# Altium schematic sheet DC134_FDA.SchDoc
size 431 x 279 mm; Date: Not shown in title block; ApprovedBy: Not shown in title block; CheckedBy: Not shown in title block; Author: Not shown in title block; CompanyName: Not shown in title block; Engineer: Not shown in title block; Organization: Not shown in title block; Address1: Not shown in title block; Address2: Not shown in title block; Address3: Not shown in title block; Address4: Not shown in title block; DocumentNumber: 3; Revision: Use project parameter SCH_Rev; SheetNumber: 3; SheetTotal: 9; PageSetup: Record=PageOptions¦CenterHorizontal=True¦CenterVertical=True¦PrintScale=1.00¦XCorrection=1.00¦YCorrection=1.00¦PrintKind=0¦BorderSize=5000000¦LeftOffset=0¦BottomOffset=0¦Orientation=2¦PaperLength=1000¦PaperWidth=1000¦Scale=100¦PaperSource=15¦PrintQuality=600¦MediaType=1¦DitherType=10¦PaperKind=Letter¦PrintScaleMode=1
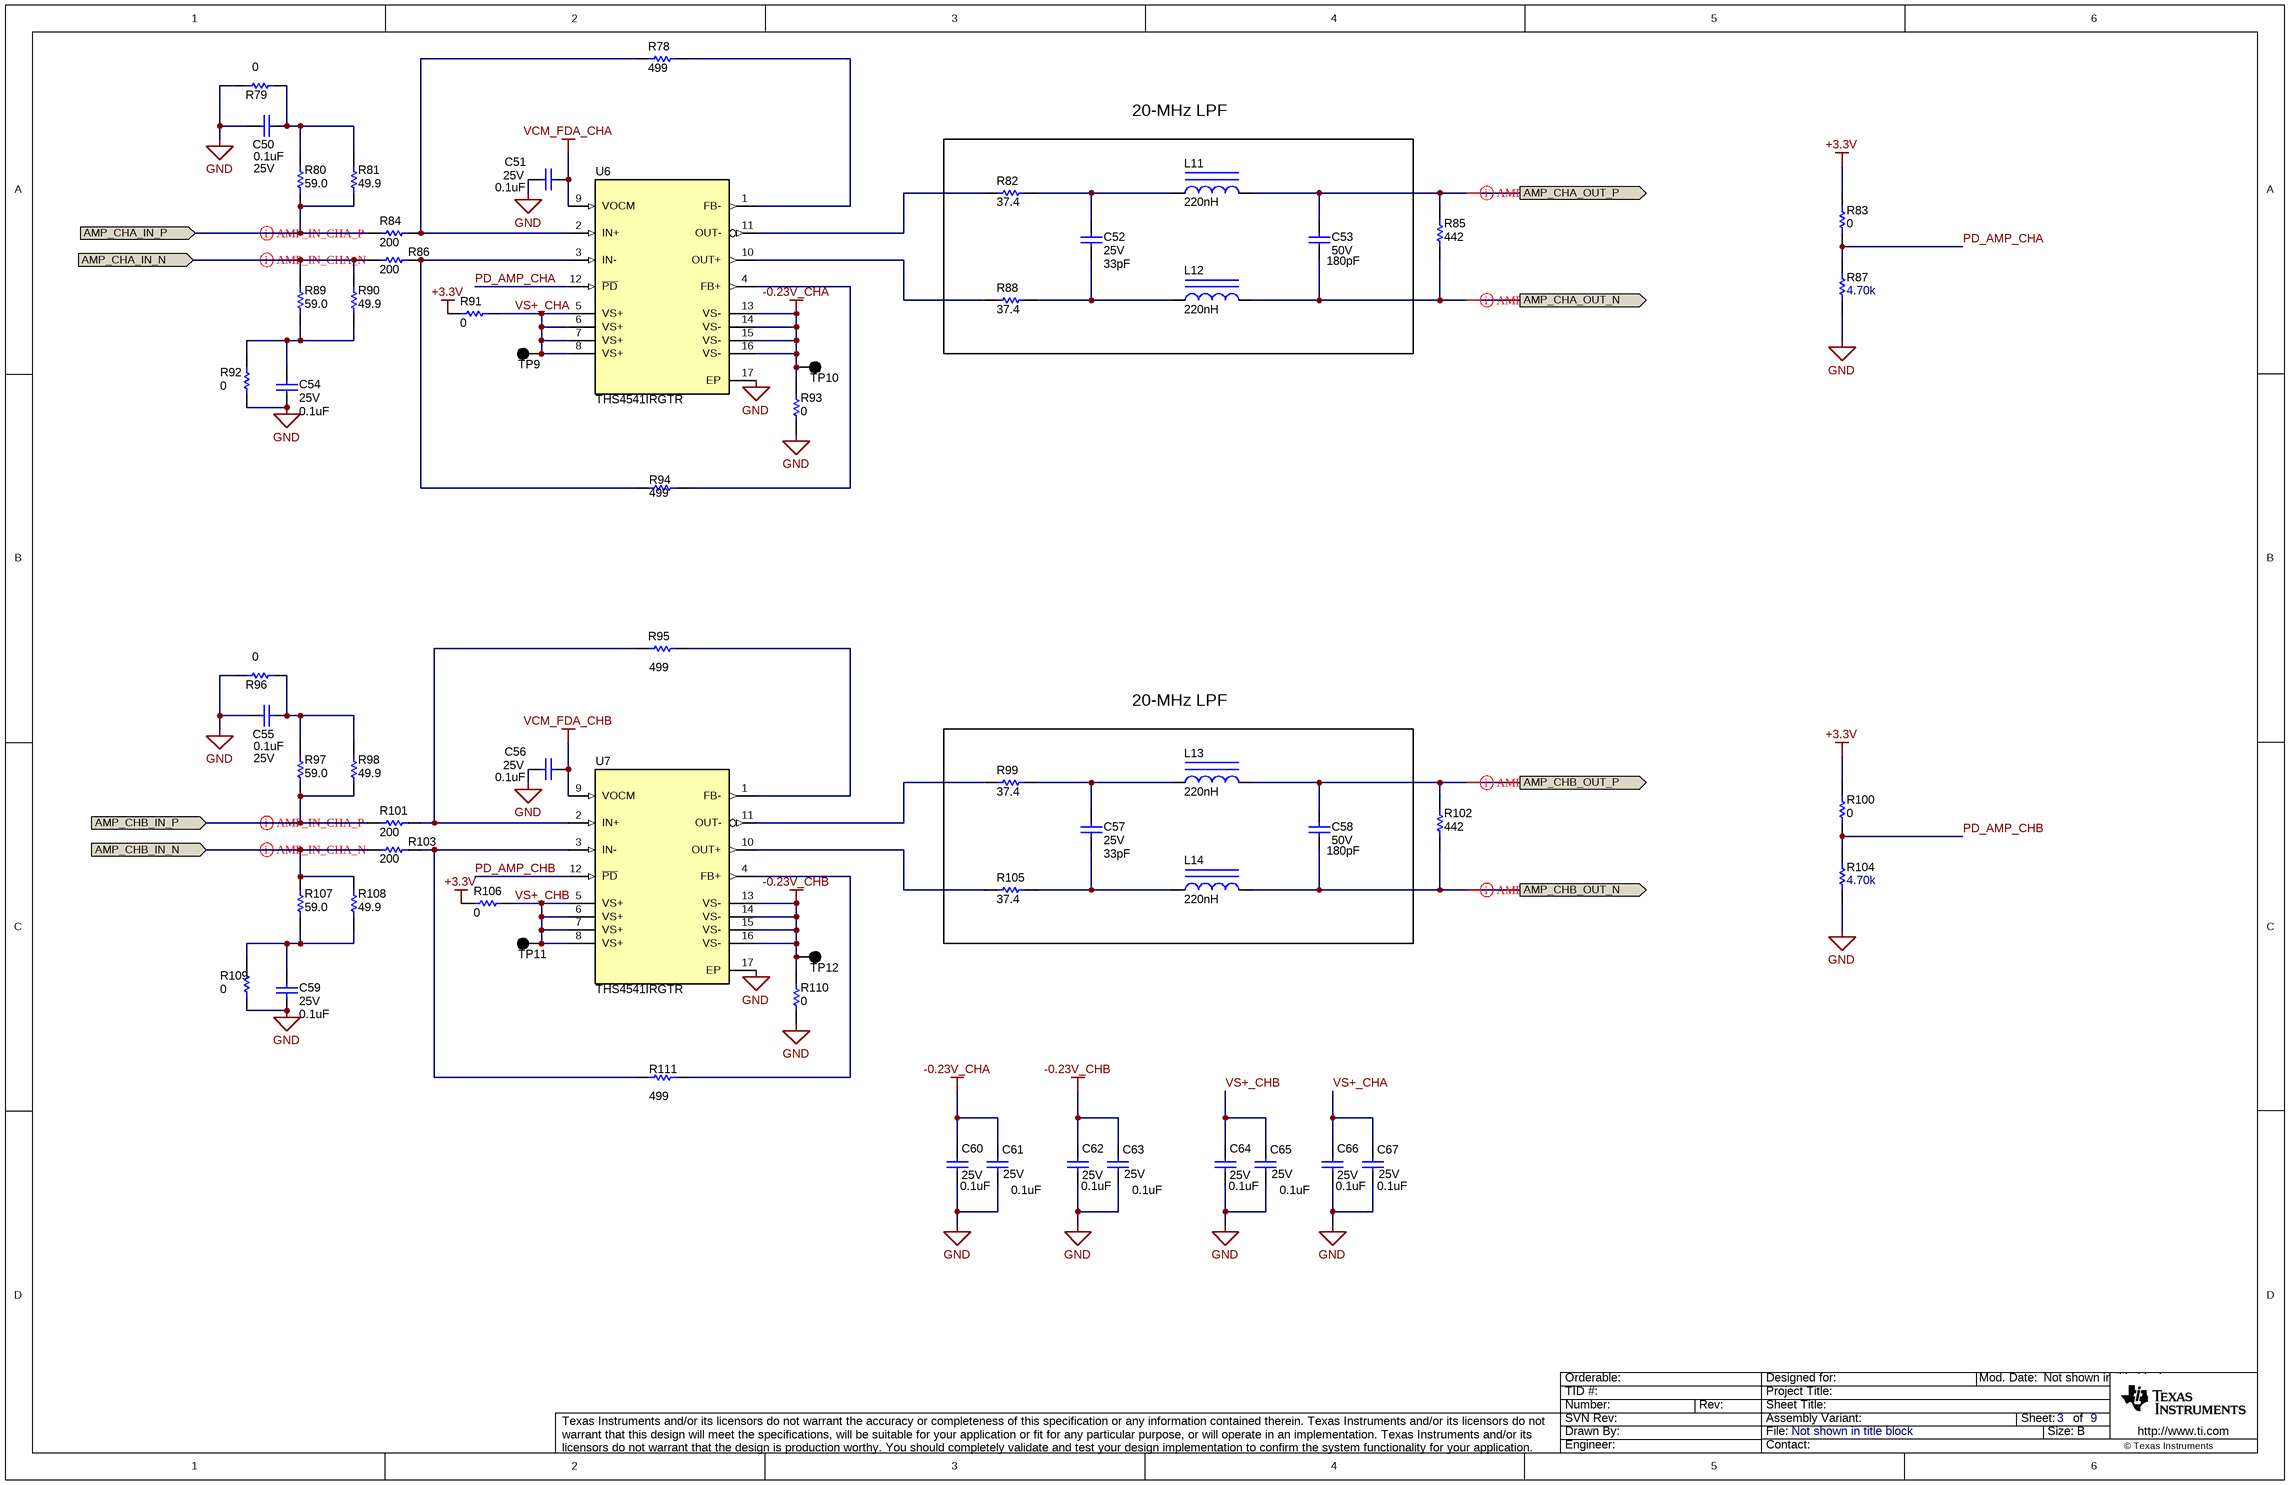
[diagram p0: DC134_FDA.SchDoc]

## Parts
C50  VDC_V: 25V  ValueDisplayed: 0.1uF  [0402]  (hidden comment: GRM155R61E104KA87D)
C51  VDC_V: 25V  ValueDisplayed: 0.1uF  [0402]  (hidden comment: GRM155R61E104KA87D)
C52  VDC_V: 25V  ValueDisplayed: 33pF  [0402]  (hidden comment: GRM1555C1E330JA01D)
C53  VDC_V: 50V  ValueDisplayed: 180pF  [0402]  (hidden comment: GRM1555C1H181JA01D)
C54  VDC_V: 25V  ValueDisplayed: 0.1uF  [0402]  (hidden comment: GRM155R61E104KA87D)
C55  VDC_V: 25V  ValueDisplayed: 0.1uF  [0402]  (hidden comment: GRM155R61E104KA87D)
C56  VDC_V: 25V  ValueDisplayed: 0.1uF  [0402]  (hidden comment: GRM155R61E104KA87D)
C57  VDC_V: 25V  ValueDisplayed: 33pF  [0402]  (hidden comment: GRM1555C1E330JA01D)
C58  VDC_V: 50V  ValueDisplayed: 180pF  [0402]  (hidden comment: GRM1555C1H181JA01D)
C59  VDC_V: 25V  ValueDisplayed: 0.1uF  [0402]  (hidden comment: GRM155R61E104KA87D)
C60  VDC_V: 25V  ValueDisplayed: 0.1uF  [0402]  (hidden comment: GRM155R61E104KA87D)
C61  value 0.1uF  VDC_V: 25V  [0402]  (hidden comment: GRM155R61E104KA87D)
C62  VDC_V: 25V  ValueDisplayed: 0.1uF  [0402]  (hidden comment: GRM155R61E104KA87D)
C63  value 0.1uF  VDC_V: 25V  [0402]  (hidden comment: GRM155R61E104KA87D)
C64  VDC_V: 25V  ValueDisplayed: 0.1uF  [0402]  (hidden comment: GRM155R61E104KA87D)
C65  value 0.1uF  VDC_V: 25V  [0402]  (hidden comment: GRM155R61E104KA87D)
C66  VDC_V: 25V  ValueDisplayed: 0.1uF  [0402]  (hidden comment: GRM155R61E104KA87D)
C67  VDC_V: 25V  ValueDisplayed: 0.1uF  [0402]  (hidden comment: GRM155R61E104KA87D)
L11  ValueDisplayed: 220nH  [IND_LQG15H]  (hidden comment: LQG15HSR22J02D)
L12  ValueDisplayed: 220nH  [IND_LQG15H]  (hidden comment: LQG15HSR22J02D)
L13  ValueDisplayed: 220nH  [IND_LQG15H]  (hidden comment: LQG15HSR22J02D)
L14  ValueDisplayed: 220nH  [IND_LQG15H]  (hidden comment: LQG15HSR22J02D)
R78  ValueDisplayed: 499  [0402]  (hidden comment: CRCW0402499RFKED)
R79  ValueDisplayed: 0  [0402]  (hidden comment: CRCW04020000Z0ED)
R80  ValueDisplayed: 59.0  [0402]  (hidden comment: CRCW040259R0FKED)
R81  ValueDisplayed: 49.9  [0402]  (hidden comment: CRCW040249R9FKED)
R82  ValueDisplayed: 37.4  [0402]  (hidden comment: CRCW040237R4FKED)
R83  ValueDisplayed: 0  [0402]  (hidden comment: CRCW04020000Z0ED)
R84  ValueDisplayed: 200  [0402]  (hidden comment: CRCW0402200RFKED)
R85  ValueDisplayed: 442  [0402]  (hidden comment: CRCW0402442RFKED)
R86  ValueDisplayed: 200  [0402]  (hidden comment: CRCW0402200RFKED)
R87  ValueDisplayed: 4.70k  [0402]  (hidden comment: ERJ-2RKF4701X)
R88  ValueDisplayed: 37.4  [0402]  (hidden comment: CRCW040237R4FKED)
R89  ValueDisplayed: 59.0  [0402]  (hidden comment: CRCW040259R0FKED)
R90  ValueDisplayed: 49.9  [0402]  (hidden comment: CRCW040249R9FKED)
R91  ValueDisplayed: 0  [0201L]  (hidden comment: CRCW02010000Z0ED)
R92  ValueDisplayed: 0  [0402]  (hidden comment: CRCW04020000Z0ED)
R93  ValueDisplayed: 0  [0201L]  (hidden comment: CRCW02010000Z0ED)
R94  ValueDisplayed: 499  [0402]  (hidden comment: CRCW0402499RFKED)
R95  ValueDisplayed: 499  [0402]  (hidden comment: CRCW0402499RFKED)
R96  ValueDisplayed: 0  [0402]  (hidden comment: CRCW04020000Z0ED)
R97  ValueDisplayed: 59.0  [0402]  (hidden comment: CRCW040259R0FKED)
R98  ValueDisplayed: 49.9  [0402]  (hidden comment: CRCW040249R9FKED)
R99  ValueDisplayed: 37.4  [0402]  (hidden comment: CRCW040237R4FKED)
R100  ValueDisplayed: 0  [0402]  (hidden comment: CRCW04020000Z0ED)
R101  ValueDisplayed: 200  [0402]  (hidden comment: CRCW0402200RFKED)
R102  ValueDisplayed: 442  [0402]  (hidden comment: CRCW0402442RFKED)
R103  ValueDisplayed: 200  [0402]  (hidden comment: CRCW0402200RFKED)
R104  ValueDisplayed: 4.70k  [0402]  (hidden comment: ERJ-2RKF4701X)
R105  ValueDisplayed: 37.4  [0402]  (hidden comment: CRCW040237R4FKED)
R106  ValueDisplayed: 0  [0201L]  (hidden comment: CRCW02010000Z0ED)
R107  ValueDisplayed: 59.0  [0402]  (hidden comment: CRCW040259R0FKED)
R108  ValueDisplayed: 49.9  [0402]  (hidden comment: CRCW040249R9FKED)
R109  ValueDisplayed: 0  [0402]  (hidden comment: CRCW04020000Z0ED)
R110  ValueDisplayed: 0  [0201L]  (hidden comment: CRCW02010000Z0ED)
R111  Res_ohm: 499  [0402]  (hidden comment: CRCW0402499RFKED)
TP9  5011  [Keystone5011]  (value not drawn)
TP10  5011  [Keystone5011]  (value not drawn)
TP11  5011  [Keystone5011]  (value not drawn)
TP12  5011  [Keystone5011]  (value not drawn)
U6  THS4541IRGTR  [RGT0016A_NV]
U7  THS4541IRGTR  [RGT0016A_NV]

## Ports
AMP_CHA_IN_N (in), AMP_CHA_IN_P (in), AMP_CHA_OUT_N (out), AMP_CHA_OUT_P (out), AMP_CHB_IN_N (in), AMP_CHB_IN_P (in), AMP_CHB_OUT_N (out), AMP_CHB_OUT_P (out)

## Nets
+3.3V: R83.2 R91.2 R100.2 R106.2
-0.23V_CHA: C60.1 C61.1 R93.2 TP10.1 U6.13(VS-) U6.14(VS-) U6.15(VS-) U6.16(VS-)
-0.23V_CHB: C62.1 C63.1 R110.2 TP12.1 U7.13(VS-) U7.14(VS-) U7.15(VS-) U7.16(VS-)
GND: C50.1 C51.1 C54.2 C55.1 C56.1 C59.2 C60.2 C61.2 C62.2 C63.2 C64.2 C65.2 C66.2 C67.2 R79.2 R87.1 R92.2 R93.1 R96.2 R104.1 R109.2 R110.1 U6.17(EP) U7.17(EP)
VCM_FDA_CHA: C51.2 U6.9(VOCM)
VCM_FDA_CHB: C56.2 U7.9(VOCM)
AMP_CHA_IN_N: R86.1 R89.2 R90.2 ; port AMP_CHA_IN_N
AMP_CHA_IN_P: R80.1 R81.1 R84.1 ; port AMP_CHA_IN_P
AMP_CHA_OUT_N: C53.2 L12.2 R85.1 ; port AMP_CHA_OUT_N
AMP_CHA_OUT_P: C53.1 L11.2 R85.2 ; port AMP_CHA_OUT_P
AMP_CHB_IN_N: R103.1 R107.2 R108.2 ; port AMP_CHB_IN_N
AMP_CHB_IN_P: R97.1 R98.1 R101.1 ; port AMP_CHB_IN_P
AMP_CHB_OUT_N: C58.2 L14.2 R102.1 ; port AMP_CHB_OUT_N
AMP_CHB_OUT_P: C58.1 L13.2 R102.2 ; port AMP_CHB_OUT_P
PD_AMP_CHA: R83.1 R87.2 U6.12(~{PD})
PD_AMP_CHB: R100.1 R104.2 U7.12(~{PD})
VS+_CHA: C66.1 C67.1 R91.1 TP9.1 U6.5(VS+) U6.6(VS+) U6.7(VS+) U6.8(VS+)
VS+_CHB: C64.1 C65.1 R106.1 TP11.1 U7.5(VS+) U7.6(VS+) U7.7(VS+) U7.8(VS+)
NetC50_2: C50.2 R79.1 R80.2 R81.2
NetC52_1: C52.1 L11.1 R82.2
NetC52_2: C52.2 L12.1 R88.2
NetC54_1: C54.1 R89.1 R90.1 R92.1
NetC55_2: C55.2 R96.1 R97.2 R98.2
NetC57_1: C57.1 L13.1 R99.2
NetC57_2: C57.2 L14.1 R105.2
NetC59_1: C59.1 R107.1 R108.1 R109.1
NetR78_1: R78.1 R84.2 U6.2(IN+)
NetR78_2: R78.2 U6.1(FB-)
NetR82_1: R82.1 U6.11(OUT-)
NetR86_2: R86.2 R94.1 U6.3(IN-)
NetR88_1: R88.1 U6.10(OUT+)
NetR94_2: R94.2 U6.4(FB+)
NetR95_1: R95.1 R101.2 U7.2(IN+)
NetR95_2: R95.2 U7.1(FB-)
NetR99_1: R99.1 U7.11(OUT-)
NetR103_2: R103.2 R111.1 U7.3(IN-)
NetR105_1: R105.1 U7.10(OUT+)
NetR111_2: R111.2 U7.4(FB+)

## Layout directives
differential pair: AMP_CHA_IN_N, AMP_CHA_IN_P, AMP_CHA_OUT_N, AMP_CHA_OUT_P, AMP_CHB_IN_N, AMP_CHB_IN_P, AMP_CHB_OUT_N, AMP_CHB_OUT_P

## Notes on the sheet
- 20-MHz LPF

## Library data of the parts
C50 C51 C55 C56 = CMP-0006607-2: CAP, CERM, 0.1 uF, 25 V, +/- 10%, X5R, 0402; Manufacturer: MuRata; TaMin_C: -55°C; Polarized: N; SizeAreaWB_mm2: 3; Value1: Unknown; U/M: EA; Value: 0.1uF; TaMax_C: 85°C; SizeZ_mm: 0.6; SizeX_mm: 1; SizeY_mm: 0.5; CompType: Capacitor; Cap_F: 100nF; AEC Category: Q200
C52 C57 = CMP-0006377-2: CAP, CERM, 33 pF, 25 V, +/- 5%, C0G/NP0, 0402; Manufacturer: MuRata; TaMin_C: -55°C; Polarized: N; SizeAreaWB_mm2: 3; Value1: Unknown; U/M: EA; Value: 33pF; TaMax_C: 125°C; SizeZ_mm: 0.6; SizeX_mm: 1; SizeY_mm: 0.5; AEC Category: Q200
C53 C58 = CMP-0006425-2: CAP, CERM, 180 pF, 50 V, +/- 5%, C0G/NP0, 0402; Manufacturer: MuRata; TaMin_C: -55°C; Polarized: N; SizeAreaWB_mm2: 3; Value1: Unknown; U/M: EA; Value: 180pF; TaMax_C: 125°C; SizeZ_mm: 0.6; SizeX_mm: 1; SizeY_mm: 0.5; AEC Category: Q200
C54 C59 C60 C62 C64 C66 C67 = CMP-0006607-2: CAP, CERM, 0.1 uF, 25 V, +/- 10%, X5R, 0402; Manufacturer: MuRata; TaMin_C: -55°C; Polarized: N; SizeAreaWB_mm2: 3; Value1: Unknown; U/M: EA; Value: 0.1uF; TaMax_C: 85°C; SizeZ_mm: 0.6; SizeX_mm: 1; SizeY_mm: 0.5; Cap_F: 100nF; AEC Category: Q200
C61 C63 C65 = CMP-0006607-2: CAP, CERM, 0.1 uF, 25 V, +/- 10%, X5R, 0402; Manufacturer: MuRata; TaMin_C: -55°C; Polarized: N; SizeAreaWB_mm2: 3; Value1: Unknown; U/M: EA; TaMax_C: 85°C; SizeZ_mm: 0.6; SizeX_mm: 1; SizeY_mm: 0.5; Cap_F: 100nF; AEC Category: Q200
L11-L14 = CMP-0058651-1: Inductor, Multilayer, Air Core, 220 nH, 0.12 A, 3.77 ohm, SMD; Manufacturer: MuRata; Isat: 0.12A @ % inductance drop; Irms: 0.12A @ C rise; Green_Lifecycle: Active; SizeAreaWB_mm2: 3; DCR_ohm: 3.77; Green_REACh: Passed; Value: 220nH; Imax_A: 1.2dA; SizeZ_mm: 0.55; SizeX_mm: 1; SizeY_mm: 0.5; Value2: 0.12A; AEC Category: Q200
R78 R94 R95 R111 = CMP-0026402-2: RES, 499, 1%, 0.063 W, AEC-Q200 Grade 0, 0402; Manufacturer: Vishay-Dale; Power_W: 63mW; TempCo: 100 ppm/C; Value_Code: 499R; Value: 499; EIA_Code: E96; SizeX_mm: 1; SizeY_mm: 0.5; SizeZ_mm: 0.6; Value2: 0.063W; AEC Qualified: Y; VDC_V: 50V; AEC Category: Q200; AEC Grade: 0
R79 R83 R92 R96 R100 R109 = CMP-0026822-3: RES, 0, 5%, 0.063 W, AEC-Q200 Grade 0, 0402; Manufacturer: Vishay-Dale; Power_W: 63mW; TempCo: 200 ppm/C; Value_Code: 0000; Value: 0; EIA_Code: E24; SizeX_mm: 1; SizeY_mm: 0.5; SizeZ_mm: 0.6; Value2: 0.063W; AEC Qualified: Y; VDC_V: 50V; AEC Category: Q200
R80 R89 R97 R107 = CMP-0026462-2: RES, 59.0, 1%, 0.063 W, AEC-Q200 Grade 0, 0402; Manufacturer: Vishay-Dale; Power_W: 63mW; TempCo: 100 ppm/C; Value_Code: 59R0; Value: 59.0; EIA_Code: E96; Res_ohm: 59; SizeX_mm: 1; SizeY_mm: 0.5; Value2: 0.063W; AEC Qualified: Y; VDC_V: 50V; AEC Category: Q200; AEC Grade: 0; SizeZ_mm: 0.6
R81 R90 R98 R108 = CMP-0026404-2: RES, 49.9, 1%, 0.063 W, AEC-Q200 Grade 0, 0402; Manufacturer: Vishay-Dale; Power_W: 63mW; TempCo: 100 ppm/C; Value_Code: 49R9; Value: 49.9; EIA_Code: E96; SizeX_mm: 1; SizeY_mm: 0.5; SizeZ_mm: 0.6; Value2: 0.063W; AEC Qualified: Y; VDC_V: 50V; AEC Category: Q200; AEC Grade: 0
R82 R88 R99 R105 = CMP-0026320-2: RES, 37.4, 1%, 0.063 W, AEC-Q200 Grade 0, 0402; Manufacturer: Vishay-Dale; Power_W: 63mW; TempCo: 100 ppm/C; Value_Code: 37R4; Value: 37.4; EIA_Code: E96; SizeX_mm: 1; SizeY_mm: 0.5; SizeZ_mm: 0.6; Value2: 0.063W; AEC Qualified: Y; VDC_V: 50V; AEC Category: Q200; AEC Grade: 0
R84 R86 R101 R103 = CMP-0026159-2: RES, 200, 1%, 0.063 W, AEC-Q200 Grade 0, 0402; Manufacturer: Vishay-Dale; Power_W: 63mW; TempCo: 100 ppm/C; Value_Code: 200R; Value: 200; EIA_Code: E96; SizeX_mm: 1; SizeY_mm: 0.5; SizeZ_mm: 0.6; Value2: 0.063W; AEC Qualified: Y; VDC_V: 50V; AEC Category: Q200; AEC Grade: 0
R85 R102 = CMP-0026382-2: RES, 442, 1%, 0.063 W, AEC-Q200 Grade 0, 0402; Manufacturer: Vishay-Dale; Power_W: 63mW; TempCo: 100 ppm/C; Value_Code: 442R; Value: 442; EIA_Code: E96; SizeX_mm: 1; SizeY_mm: 0.5; SizeZ_mm: 0.6; Value2: 0.063W; AEC Qualified: Y; VDC_V: 50V; AEC Category: Q200; AEC Grade: 0
R87 R104 = CMP-0026700-1: RES, 4.70 k, 1%, 0.1 W, 0402; Manufacturer: Panasonic; Power_W: 100mW; TempCo: 100 ppm/C; Value_Code: 4k70; U/M: EA; Value: 4.70k; Res_ohm: 4.7k; SizeX_mm: 1; SizeY_mm: 0.5; SizeZ_mm: 0.6; Value2: 0.1W; CompType: Resistor; VDC_V: 50V; AEC Category: Q200
R91 R93 R106 R110 = CMP-0027008-4: RES, 0, 5%, 0.05 W, 0201; Manufacturer: Vishay-Dale; Power_W: 50mW; TempCo: ppm/C; Value_Code: 0000; Value: 0; EIA_Code: E24; SizeX_mm: 0.6; SizeY_mm: 0.3; SizeZ_mm: 0.26; Value2: 0.05W; SizeArea_mm2: 0.18; AEC Qualified: N; AEC Category: Q200
TP9-TP12 = CMP-0055148-1: Test Point, Multipurpose, Black, TH; Manufacturer: Keystone; CNHeader: FALSE; Green_Lifecycle: Active; Green_REACh: Passed; ContactFinish: Silver; CT: TRUE
U6 U7 = CMP-0065559-3: High-Speed Differential I/O Amplifier, RGT0016A (VQFN-16); Alternate PartNumber: THS4541IRGTT; Manufacturer: Texas Instruments; SizeZ_mm: 4; SizeArea_mm2: 16; CompType: IC; SizeAreaWB_mm2: 25; AEC Category: Q200; AEC Qualified: N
